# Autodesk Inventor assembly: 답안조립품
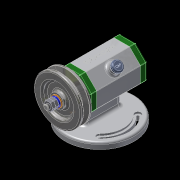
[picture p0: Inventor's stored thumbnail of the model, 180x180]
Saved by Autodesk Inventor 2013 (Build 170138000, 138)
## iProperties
Created: 2017-06
Part Number: 답안조립품
Document SubType Name: Assembly
Designer: Administrator
Author: Administrator
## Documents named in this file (14)
- C:\Users\Administrator\Desktop\470608V1015\답안조립품.iam
- C:\Users\Administrator\Desktop\470608V1015\본체.ipt
- C:\Users\Administrator\Desktop\470608V1015\축.ipt
- C:\Users\Administrator\Desktop\470608V1015\키 3 x 3 x 12.ipt
- C:\Users\Administrator\Desktop\470608V1015\베어링 15 x 32 x 9.ipt
- C:\Users\Administrator\Desktop\470608V1015\앞커버.ipt
- C:\Users\Administrator\Desktop\470608V1015\오일 실 15 25 7.ipt
- C:\Users\Administrator\Desktop\470608V1015\볼트 M4 x 12.ipt
- C:\Users\Administrator\Desktop\470608V1015\뒤커버.ipt
- C:\Users\Administrator\Desktop\470608V1015\V벨트풀리.ipt
- C:\Users\Administrator\Desktop\470608V1015\고무캡.ipt
- C:\Users\Administrator\Desktop\470608V1015\너트 M 8.ipt
- C:\Users\Administrator\Desktop\470608V1015\와셔 8x17.ipt
- C:\Users\Administrator\Desktop\470608V1015\스프링와셔 8.ipt
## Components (2 placed, 2 different names)
1. V벨트풀리:1
2. 고무캡:1
